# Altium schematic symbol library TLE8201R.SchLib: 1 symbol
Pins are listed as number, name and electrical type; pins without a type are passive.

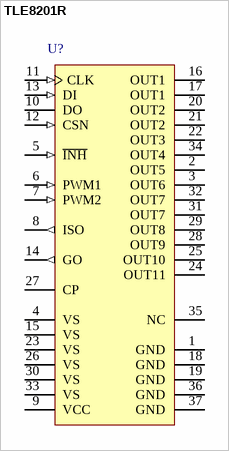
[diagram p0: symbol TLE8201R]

## TLE8201R
designator U?
Door Module Power IC, -40 to 150 degC, PG-DSO-36-27, Reel, Green; Manufacturer: Infineon; PartNumber: TLE8201R; Green: TRUE; Group: Door Module IC´s; IPeak: 8 A peak for OUT 1.2 ; 6.25 A peak for OUT 7; Iq: Icc_q = 1 uA max ; Is_q = 5 uA max; Iq (typ): 0.2 uA; 2.5 uA; Operating Range: 8 to 20 V; 5 to 40 V; Protect: Overtemp. e.a.
footprint INF-PG-DSO-36-27_N (SOP, 36-Leads, Body 15.9x11mm, Pitch 0.65mm, Thermal Pad 15.84x6mm, IPC Medium Density)
footprint INF-PG-DSO-36-27_L (SOP, 36-Leads, Body 15.9x11mm, Pitch 0.65mm, Thermal Pad 15.84x6mm, IPC High Density)
footprint INF-PG-DSO-36-27_M (SOP, 36-Leads, Body 15.9x11mm, Pitch 0.65mm, Thermal Pad 15.84x6mm, IPC Low Density)
pins: 1 GND (power) "Ground; internally connected to cooling tab (heat slug).", 2 OUT5 (power) "Power-Output of half-bridge 5; DMOS half-bridge", 3 OUT6 (power) "Power-Output of half-bridge 6; DMOS half-bridge.", 4 VS (power) "Power supply; needs decoupling capacitors to GND. > 47uF electrolytic in parallel with 100nF ceramic is recommended. All Vs pins must be connected externally", 5 ~{INH} (in) "Inhibit; active low. Sets the device in sleep mode with low current consumption when left open or pulled to LOW. Has an internal pull down current source", 6 PWM1 (in) "Logic Input for direct power stage control; direct input to control the high-side switches selected by the SPI xsel1 bits in control register CtrlReg01", 7 PWM2 (in) "Logic Input for direct power stage control; direct input to control the switches selected by the SPI xsel2 bits in control register CtrlReg11", 8 ISO (out) "Current sense output; Mirrors the current of the high-side switch selected by the current sense multiplexer control bits ISx", 9 VCC (power) "Logic Supply Voltage; needs decoupling capacitors to GND (pin 1). 10uF electrolytic in parallel with 10nF ceramic is recommended", 10 DO (hiz) "Serial Data Output; Transfers data to the master when the chip is selected by CSN=LOW. Data transmission is synchronized by CLK, DO state is changed on the rising edge of CLK. The most significant bit (MSB) is transferred (See Datasheet)", 11 CLK (in) "Serial Data Clock Input; Receives the clock signal from the master and clocks the SPI shift register. Has an internal pull down current source", 12 CSN (in) "Serial Port Chip Select Not Input; SPI communication is enabled by pulling CSN to LOW. CLK must be LOW during the transition of CSN. The CSN-pin has an internal pull-up current source", 13 DI (in) "Serial Data Input; Receives serial data from the master when the chip is selected by CSN=LOW. Data transmission is synchronized by CLK. Data are accepted on the falling edge of CLK. The LSB is transferred first. The DI-pin (See Datasheet)", 14 GO (out) "Gate Out; Charge pump output to drive the gate of external n-channel MOS-FET for reverse polarity protection", 15 VS (power) "Power supply; needs decoupling capacitors to GND. > 47uF electrolytic in parallel with 100nF ceramic is recommended. All Vs pins must be connected externally", 16 OUT1 (power) "Power-Output of half-bridge 1; DMOS half-bridge.", 17 OUT1 (power) "Power-Output of half-bridge 1; DMOS half-bridge.", 18 GND (power) "Ground; internally connected to cooling tab (heat slug).", 19 GND (power) "Ground; internally connected to cooling tab (heat slug).", 20 OUT2 (power) "Power-Output of half-bridge 2; DMOS half-bridge.", 21 OUT2 (power) "Power-Output of half-bridge 2; DMOS half-bridge.", 22 OUT3 (power) "Power-Output of half-bridge 3; DMOS half-bridge", 23 VS (power) "Power supply; needs decoupling capacitors to GND. > 47uF electrolytic in parallel with 100nF ceramic is recommended. All Vs pins must be connected externally", 24 OUT11 (power) "Power Output of high-side switch 11; DMOS high-side switch", 25 OUT10 (power) "Power Output of high-side switch 10; DMOS high-side switch", 26 VS (power) "Power supply; needs decoupling capacitors to GND. > 47uF electrolytic in parallel with 100nF ceramic is recommended. All Vs pins must be connected externally", 27 CP "Charge Pump; pin for optional external charge-pump reservoir capacitor. 3.3 nF to Vs is recommended", 28 OUT9 (power) "Power-Output of high-side switch 9; DMOS high-side switch", 29 OUT8 (power) "Power-Output of high-side switch 8; DMOS high-side switch", 30 VS (power) "Power supply; needs decoupling capacitors to GND. > 47uF electrolytic in parallel with 100nF ceramic is recommended. All Vs pins must be connected externally", 31 OUT7 (power) "Power Output of high-side switch 7; DMOS high-side switch", 32 OUT7 (power) "Power Output of high-side switch 7; DMOS high-side switch", 33 VS (power) "Power supply; needs decoupling capacitors to GND. > 47uF electrolytic in parallel with 100nF ceramic is recommended. All Vs pins must be connected externally", 34 OUT4 (power) "Power-Output of half-bridge 4; DMOS half-bridge", 35 NC "Not connected", 36 GND (power) "Ground; internally connected to cooling tab (heat slug).", 37 GND (power) "Cooling tab, internally connected to GND; to reduce thermal resistance place cooling areas and thermal vias on PCB."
